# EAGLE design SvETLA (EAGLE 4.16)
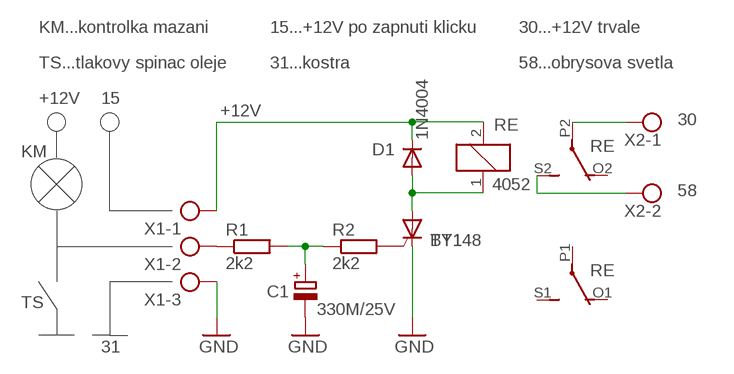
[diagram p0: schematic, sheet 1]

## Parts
C1  330M/25V  CPOL-EUE5-8.5  [E5-8,5]
D1  1N4004  [DO41-10]
R1  2k2  R-EU_0204/5  [0204/5]
R2  2k2  R-EU_0204/5  [0204/5]
RE  4052  [F4052]
TY1  BT148  [SOT82S]
X1  W237-103  [W237-103]
X2  W237-102  [W237-102]

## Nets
30: RE.P2(3:P) X2.1
58: RE.S2(3:S) X2.2
+12V: D1.C RE.2 X1.1
G: R2.2 TY1.G
GND: C1.- TY1.C X1.3
RELE: D1.A RE.1 TY1.A
TS: R1.1 X1.2
UC: C1.+ R1.2 R2.1
Unconnected: RE.O1(2:O) RE.O2(3:O) RE.P1(2:P) RE.S1(2:S)

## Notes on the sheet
- KM...kontrolka mazani | 15...+12V po zapnuti klicku | 30...+12V trvale
- TS...tlakovy spinac oleje | 31...kostra | 58...obrysova svetla
- +12V | 15 | +12V
- 30
- KM
- 58
- TS
- 31

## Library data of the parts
C1 = rcl:CPOL-EU: POLARIZED CAPACITOR, European symbol
D1 = diode:1N4004: DIODE
R1 R2 = rcl:R-EU_: RESISTOR, European symbol
RE = relay:4052: RELAY 2 x switch, Finder
TY1 = triac:BT148: THYRISTOR
X1 = con-wago-500:W237-103: WAGO SCREW CLAMP
X2 = con-wago-500:W237-102: WAGO SCREW CLAMP

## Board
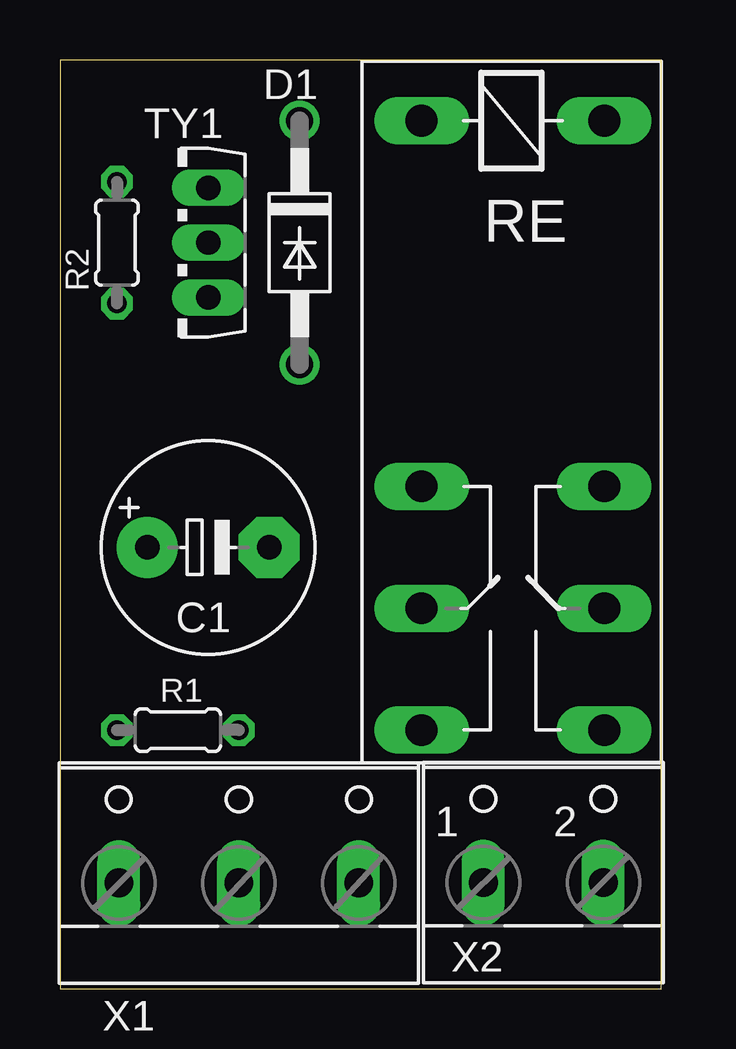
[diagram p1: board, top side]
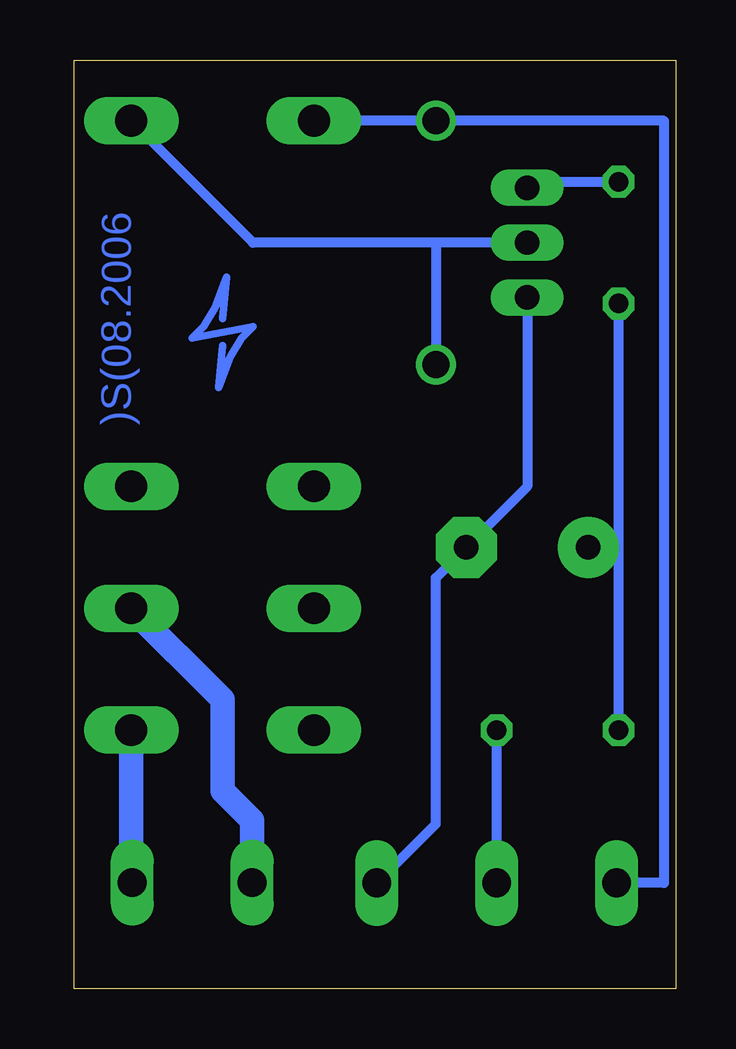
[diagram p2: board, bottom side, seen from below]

Size 25.07 x 38.73 mm. Coordinates in mm from the lower left corner, seen from the top.
Outline: 0,0 25.07,0 25.07,38.73 0,38.73 0,0
Copper layers (1*16): Top 0.035mm / dielectric 1.5mm / Bottom 0.035mm
Design rules "default": minimum track width 10mil, minimum drill 24mil, track to track 8mil, track to pad 8mil, pad to pad 8mil, via to via 8mil, smd to smd 8mil, copper to edge 40mil, drill to drill 8mil, minimum pad ring 10mil, minimum via ring 8mil, stop-mask expansion 4mil, vias tented up to drill 0mil, thermal gap 10mil

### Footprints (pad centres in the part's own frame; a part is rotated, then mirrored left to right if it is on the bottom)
E5-8,5 = drill 1.016 pad 2.54 round: + -2.54,0 | drill 1.016 pad 2.54 octagon: - 2.54,0
DO41-10 = drill 1.118 round: A 5.08,0; C -5.08,0
0204/5 = drill 0.813 octagon: 1 -2.54,0; 2 2.54,0
F4052 = drill 1.321 long: 1 -3.81,3.81; 2 -3.81,-3.81; O1 11.43,-3.81; O2 11.43,3.81; P1 16.51,-3.81; P2 16.51,3.81; S1 21.59,-3.81; S2 21.59,3.81
SOT82S = drill 1.016 long: A 0,-1.27; C -2.286,-1.27; G 2.286,-1.27
W237-103 = drill 1.194 long: 1 -5,-1.29; 2 0,-1.29; 3 5,-1.29
W237-102 = drill 1.194 long: 1 -2.5,-1.27; 2 2.5,-1.27

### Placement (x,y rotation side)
C1  6.19,18.41 0 top
D1  9.99,31.11 270 top
R1  4.91,10.79 180 top
R2  2.38,31.11 90 top
RE  18.89,32.38 270 top
TY1  4.91,31.11 90 top
X1  7.46,5.71 0 top
X2  20.16,5.71 0 top

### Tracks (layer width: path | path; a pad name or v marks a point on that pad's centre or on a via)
30
  Bottom 1.016: X2.1 17.66,7.02 18.89,8.25 18.89,12.06 RE.P2
58
  Bottom 0.406: X2.2 22.7,4.44
  Bottom 1.016: 22.7,4.44 RE.S2
+12V
  Bottom 0.406: X1.1 0.47,4.42 0.47,36.19 D1.C RE.2
G
  Bottom 0.406: TY1.G 5.93,33.65 R2.2
GND
  Bottom 0.406: X1.3 9.99,6.88 9.99,17.14 C1.- 6.19,20.95 TY1.C
RELE
  Bottom 0.406: RE.1 17.62,31.11 9.99,31.11 | TY1.A 9.99,31.11 | 9.99,31.11 D1.A
S$1
  Bottom 0.305: 18.89,27.93 18.73,29.68 19.2,28.41 19.68,27.62 20.16,27.14 17.62,27.62 18.09,27.14 18.57,26.35 19.04,25.08 18.89,26.82
TS
  Bottom 0.406: X1.2 R1.1
UC
  Bottom 0.406: 2.38,18.41 R2.1 | R1.2 2.38,18.41 | 2.38,18.41 C1.+

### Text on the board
Bottom: )S(08.2006
Document: 15 | TS | 31 | 30 | 58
